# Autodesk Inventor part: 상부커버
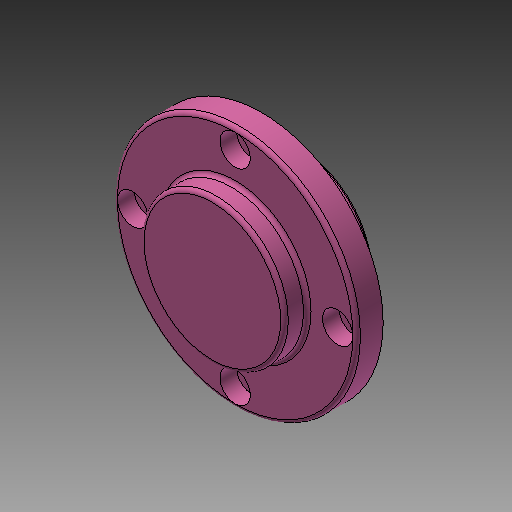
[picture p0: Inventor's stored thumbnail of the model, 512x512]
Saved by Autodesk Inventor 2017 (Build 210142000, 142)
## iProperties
Created: 2018-09
Part Number: 상부커버
Document SubType Name: Modeling
Density: 2.71 g/cm^3
Material: 알루미늄 6061
Mass: 110.394 g
Surface Area: 100.123 cm^2
Volume: 40.7359 cm^3
Appearance: 분홍색
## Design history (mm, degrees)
sketch "스케치1"
  geometry: C1 r 20 at (0, 0); C2 r 32 at (0, 0); 1 further point
  constraints: 2 centre point, 2 coincident
  dimensions: "d35" = 40 diameter of C1; "d36" = 64 diameter of C2
extrude "돌출1" new body sketch "스케치1" distance "d0" = 7; taper "d1" = 0 deg
extrude "돌출2" join sketch "스케치1" distance "d2" = 10; taper "d3" = 0 deg
sketch "스케치2"
  geometry: C1 r 19 at (0, 0); 1 further point
  constraints: 1 centre point, 1 coincident
  dimensions: "d4" = 38 diameter of C1
extrude "돌출3" join sketch "스케치2" distance "d5" = 6; taper "d6" = 0 deg
fillet "모깎기1" dims "d7" = 1
fillet "모깎기2" dims "d8" = 1
sketch "스케치4" dims "d37" = 54
  geometry: C1 r 20 at (0, 0) reference; 2 further points
  constraints: 2 vertical alignment, 1 coincident, 2 other
hole "구멍2" sketch "스케치4" at (0, 27) diameter "d28" = 4.5; stored, may be unused: countersink angle "d32" = 90 deg, drill point angle "d34" = 118 deg; dims "d29" = 6, "d30" = 8, "d31" = 4.4, "d33" = 8
fillet "모깎기3" dims "d19" = 1
chamfer "모따기1" distance "d20" = 1; stored, may be unused: second distance "d21" = 2, angle "d22" = 45 deg
node "솔리드1"
pattern_circular "원형 패턴2" dims angle "d39" = 360 deg
node "투영된 루프1"
